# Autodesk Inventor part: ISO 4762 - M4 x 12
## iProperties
Created: 2003-11
Part Number: ISO 4762 - M4 x 12
Material: Standard
Catalog Web Link: file:///C:/Programme/Autodesk/Inventor 5.3/Content/Din/index.htm?doNavigateId=7A3AD6F1-C431-11D4-A9F1-0080AD303E0A|311998ABB16811D4BA6900C04F798F98|true
Document SubType Name: Standard Catalog Part
Designer: A14S8
Control State: 0
Master: False
Checked Out: False
Shininess: 20.0
Angle Display Precision: 2
Document Length Units: 11269
Document Angle Units: 11279
Document Time Units: 11290
Document Mass Units: 11283
Document Length Units Precision: 3
Document Angle Units Precision: 2
Compacted: True
Density: 0.0
Volumn: 0.0
Area: 0.0
PropertySet Name: Model Information
Author: A14S8
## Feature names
1. Basis1
